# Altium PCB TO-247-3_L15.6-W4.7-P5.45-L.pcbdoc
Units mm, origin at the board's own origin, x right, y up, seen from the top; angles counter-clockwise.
Board outline 28.46 x 18.36 mm, 2 copper layers (Top Layer, Bottom Layer), stack 0 mm thick; 1 components, 0 nets, 3 pads, 0 vias.
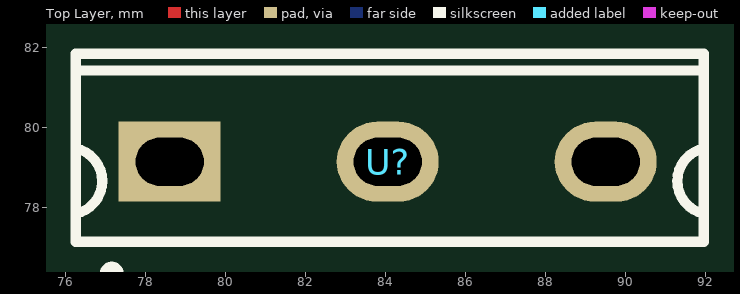
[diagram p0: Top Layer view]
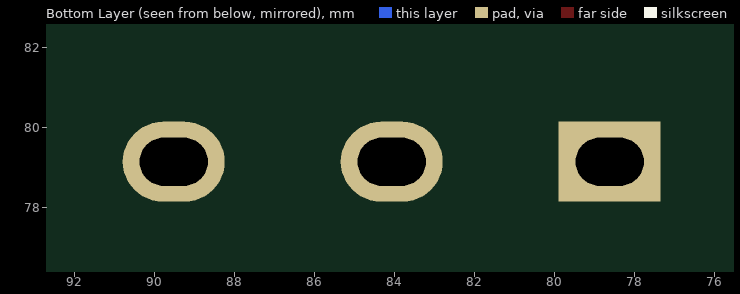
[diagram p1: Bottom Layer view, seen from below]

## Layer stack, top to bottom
Top Layer: signal copper (thickness not stored)
Bottom Layer: signal copper (thickness not stored)

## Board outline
98.314,69.85 69.85,69.85 69.85,88.21 98.314,88.21

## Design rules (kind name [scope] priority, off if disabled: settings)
PasteMaskExpansion "Paste Mask Expansion" [All] p1: expansion=0
SolderMaskExpansion "Solder Mask Expansion" [IsVia] p1: expansion=-25.4 istentingtop=TRUE
SolderMaskExpansion "Solder Mask Expansion" [All] p2: expansion=0.051 istentingtop=FALSE

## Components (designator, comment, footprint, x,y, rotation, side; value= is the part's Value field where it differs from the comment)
U? "" TO-247-3_L15.6-W4.7-P5.45-L 84.06,79.15 r0 top

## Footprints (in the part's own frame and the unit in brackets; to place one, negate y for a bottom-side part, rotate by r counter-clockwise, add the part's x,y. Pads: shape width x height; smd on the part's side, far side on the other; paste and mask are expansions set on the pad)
TO-247-3_L15.6-W4.7-P5.45-L [mm]
  rect 2.55x2 hole 1.2 slot 1.7 at 0 deg: 1(-5.45,0)
  oval 2.55x2 hole 1.2 slot 1.7 at 0 deg: 2(0,0) 3(5.45,0)
  silkscreen extent -7.8,-2.95 7.9,2.7

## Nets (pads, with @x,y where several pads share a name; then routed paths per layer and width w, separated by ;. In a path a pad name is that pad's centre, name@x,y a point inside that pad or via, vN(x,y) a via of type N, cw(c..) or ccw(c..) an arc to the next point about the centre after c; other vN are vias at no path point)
pads on no net: U?.1 U?.2 U?.3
